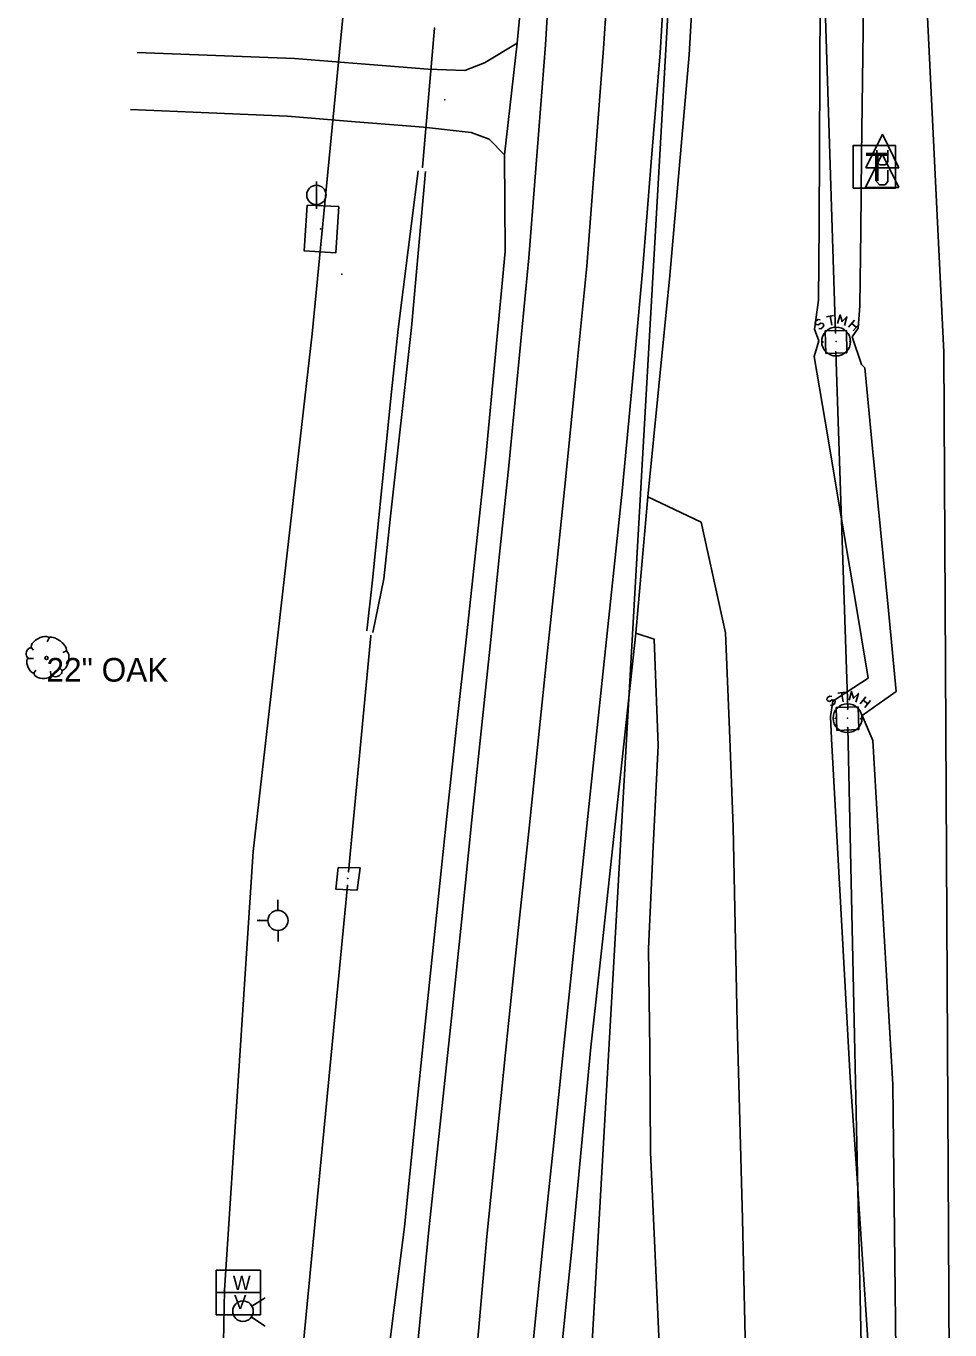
# Model space of a CAD drawing. Extents: x 1930288 to 1941089, y 588389 to 611475.
# Drawn here: x 1930793.7 to 1930989.2, y 598451.6 to 598727.5 of the extents above; entities that cross this region are included whole.
import ezdxf

# ---------------------------------------------------------------- set-up
doc = ezdxf.new("R2010")
doc.units = 0
for name, color, linetype in [('S_BASELINE', 7, 'Continuous'), ('S_DITCHLINE', 7, 'Continuous'), ('S_DRG_PT_SYM', 7, 'Continuous'), ('S_DRIVEWAY', 7, 'Continuous'), ('S_DROP_INLET', 7, 'Continuous'), ('S_EDGE_CONCRETE', 7, 'Continuous'), ('S_EDGE_PAVEMENT', 7, 'Continuous'), ('S_MSC_PT_SYM', 7, 'Continuous'), ('S_PAVEMENT_CROWN', 7, 'Continuous'), ('S_SANITARY_SEWER', 7, 'Continuous'), ('S_SHOULDER', 7, 'Continuous'), ('S_SIDE_DRAIN', 7, 'Continuous'), ('S_STORM_SEWER', 7, 'Continuous'), ('S_TELEPHONE_UTILITIES', 7, 'Continuous'), ('S_TREE', 7, 'Continuous'), ('S_TREE_ANNOT', 7, 'Continuous'), ('S_UNDERGROUND_CABLE', 7, 'Continuous'), ('S_UTILITY_POLE', 7, 'Continuous'), ('S_UTL_PT_SYM', 7, 'Continuous'), ('S_WATER_UTILITIES', 7, 'Continuous')]:
    doc.layers.add(name, color=color, linetype=linetype)

msp = doc.modelspace()

# ---------------------------------------------------------------- linework, layer by layer
at = {"layer": 'S_BASELINE'}
msp.add_line((1930894.27, 598110.49), (1930946.09, 599020.44), dxfattribs=at)
at = {"layer": 'S_DITCHLINE'}
for points in [[(1930961.8, 598733.51), (1930961.71, 598717.5), (1930961.63, 598701.5), (1930961.54, 598685.49), (1930961.45, 598669.49), (1930960.6, 598663.4), (1930961.51, 598660.89), (1930960.5, 598657.61), (1930963.36, 598640.59), (1930966.22, 598623.57), (1930969.09, 598606.55), (1930971.95, 598589.53), (1930964.42, 598584.67), (1930963.99, 598581.42), (1930964.18, 598576.71), (1930965.17, 598558.78), (1930966.16, 598540.86), (1930967.15, 598522.93), (1930968.14, 598505.01), (1930969.43, 598485.78), (1930970.71, 598466.55), (1930972, 598447.33)], [(1930970.91, 598731.9), (1930970.72, 598716.01), (1930970.54, 598700.12), (1930970.36, 598684.23), (1930970.18, 598668.34), (1930969.78, 598663.58), (1930968.54, 598661.77), (1930970.49, 598655.92), (1930971.21, 598655.22), (1930972.88, 598638.09), (1930974.55, 598620.96), (1930976.21, 598603.83), (1930977.88, 598586.7), (1930970.67, 598581.64), (1930972.93, 598576.35), (1930973.98, 598558.14), (1930975.03, 598539.93), (1930976.08, 598521.73), (1930977.13, 598503.52), (1930977.35, 598484.74), (1930977.56, 598465.96), (1930977.77, 598447.19)], [(1930876.67, 598696.88), (1930874.56, 598680.13), (1930872.44, 598663.37), (1930871.08, 598650.09), (1930869.72, 598636.8), (1930868.36, 598623.52), (1930867, 598610.24), (1930865.86, 598599.56)], [(1930878.23, 598696.7), (1930876.76, 598680.21), (1930875.28, 598663.71), (1930873.81, 598650.42), (1930872.34, 598637.12), (1930870.87, 598623.83), (1930869.4, 598610.54), (1930867.1, 598599.2)]]:
    msp.add_lwpolyline(points, dxfattribs=at)
at = {"layer": 'S_DRG_PT_SYM'}
for points in [[(1930880.15, 598727.06), (1930880.15, 598727.11), (1930880.15, 598727.06), (1930880.1, 598727.06), (1930880.15, 598727.06), (1930880.15, 598727.01), (1930880.15, 598727.06), (1930880.2, 598727.06)], [(1930877.61, 598697.64), (1930877.61, 598697.69), (1930877.61, 598697.64), (1930877.56, 598697.64), (1930877.61, 598697.64), (1930877.61, 598697.58), (1930877.61, 598697.64), (1930877.66, 598697.64)], [(1930866.67, 598598.49), (1930866.67, 598598.54), (1930866.67, 598598.49), (1930866.62, 598598.49), (1930866.67, 598598.49), (1930866.67, 598598.44), (1930866.67, 598598.49), (1930866.72, 598598.49)], [(1930861.78, 598547.12), (1930861.78, 598547.17), (1930861.78, 598547.12), (1930861.73, 598547.12), (1930861.78, 598547.12), (1930861.78, 598547.07), (1930861.78, 598547.12), (1930861.83, 598547.12)]]:
    msp.add_lwpolyline(points, dxfattribs=at)
at = {"layer": 'S_DRIVEWAY'}
for points in [[(1930897.67, 598723.87), (1930890.76, 598719.75), (1930886.59, 598718.14), (1930878.82, 598718.39), (1930864.66, 598719.5), (1930850.51, 598720.61), (1930833.87, 598721.28), (1930817.23, 598721.95)], [(1930815.79, 598709.82), (1930832.4, 598709.13), (1930849.02, 598708.44), (1930863.42, 598707.27), (1930877.81, 598706.1), (1930887.94, 598705.01), (1930891.69, 598703.54), (1930894.96, 598700.28)]]:
    msp.add_lwpolyline(points, dxfattribs=at)
at = {"layer": 'S_DROP_INLET'}
for points in [[(1930962.97, 598658.25), (1930962.86, 598663.03), (1930967.35, 598663.08), (1930967.43, 598658.33)], [(1930967.43, 598658.33), (1930962.97, 598658.25)], [(1930969.84, 598583.46), (1930965.19, 598583.3)], [(1930965.19, 598583.3), (1930965.32, 598578.46), (1930969.93, 598578.64), (1930969.84, 598583.46)], [(1930859.77, 598549.45), (1930859.26, 598544.89), (1930863.76, 598544.66), (1930864.39, 598549.38)], [(1930864.39, 598549.38), (1930859.77, 598549.45)]]:
    msp.add_lwpolyline(points, dxfattribs=at)
at = {"layer": 'S_EDGE_CONCRETE'}
for points in [[(1930853.24, 598689.61), (1930852.6, 598679.92), (1930859.27, 598679.52), (1930859.91, 598689.36)], [(1930859.91, 598689.36), (1930853.24, 598689.61)]]:
    msp.add_lwpolyline(points, dxfattribs=at)
at = {"layer": 'S_EDGE_PAVEMENT'}
for points in [[(1930904.92, 598744.7), (1930903.67, 598723.53), (1930901.89, 598701), (1930900.1, 598678.48), (1930897.99, 598656.48), (1930895.88, 598634.48), (1930893.93, 598615.75), (1930891.98, 598597.02), (1930890.03, 598578.29), (1930888.08, 598559.56), (1930885.91, 598538.55), (1930883.74, 598517.54), (1930881.36, 598495.14), (1930878.97, 598472.74), (1930877.33, 598456.1), (1930875.68, 598439.46)], [(1930929.16, 598742.91), (1930927.89, 598721.82), (1930926.03, 598698.68), (1930924.17, 598675.54), (1930922.04, 598652.3), (1930919.9, 598629.06), (1930917.99, 598611.04), (1930916.07, 598593.01), (1930914.16, 598574.98), (1930912.24, 598556.95), (1930909.92, 598534.68), (1930907.6, 598512.4), (1930905.38, 598491.18), (1930903.15, 598469.95), (1930901.49, 598453.28), (1930899.84, 598436.61)], [(1930925.3, 598627.92), (1930936.56, 598622.51), (1930941.76, 598599.13), (1930942.55, 598578.56), (1930943.33, 598557.99), (1930943.76, 598537.25), (1930944.18, 598516.5), (1930944.75, 598495.82), (1930945.32, 598475.13), (1930945.82, 598453.1), (1930946.32, 598431.07), (1930946.01, 598409.55), (1930945.7, 598388.03), (1930944.74, 598367.17), (1930943.78, 598346.31)], [(1930924.96, 598333.18), (1930925.73, 598350.75), (1930926.49, 598368.33), (1930927.26, 598385.9), (1930928.03, 598403.47), (1930927.92, 598424.51), (1930927.81, 598445.55), (1930926.85, 598467.37), (1930925.9, 598489.18), (1930925.69, 598510.76), (1930925.47, 598532.34), (1930926.46, 598553.81), (1930927.46, 598575.27), (1930926.63, 598597.79), (1930922.74, 598599.04)]]:
    msp.add_lwpolyline(points, dxfattribs=at)
at = {"layer": 'S_MSC_PT_SYM'}
for points in [[(1930882.32, 598711.9), (1930882.32, 598711.95), (1930882.32, 598711.9), (1930882.27, 598711.9), (1930882.32, 598711.9), (1930882.32, 598711.85), (1930882.32, 598711.9), (1930882.37, 598711.9)], [(1930856.07, 598684.59), (1930856.07, 598684.64), (1930856.07, 598684.59), (1930856.02, 598684.59), (1930856.07, 598684.59), (1930856.07, 598684.54), (1930856.07, 598684.59), (1930856.12, 598684.59)], [(1930965.03, 598662.59), (1930965.03, 598662.64), (1930965.03, 598662.59), (1930964.98, 598662.59), (1930965.03, 598662.59), (1930965.03, 598662.54), (1930965.03, 598662.59), (1930965.08, 598662.59)], [(1930962.35, 598660.66), (1930962.35, 598660.71), (1930962.35, 598660.66), (1930962.3, 598660.66), (1930962.35, 598660.66), (1930962.35, 598660.61), (1930962.35, 598660.66), (1930962.4, 598660.66)], [(1930965.07, 598658.54), (1930965.07, 598658.59), (1930965.07, 598658.54), (1930965.02, 598658.54), (1930965.07, 598658.54), (1930965.07, 598658.49), (1930965.07, 598658.54), (1930965.12, 598658.54)], [(1930968.04, 598660.78), (1930968.04, 598660.83), (1930968.04, 598660.78), (1930967.99, 598660.78), (1930968.04, 598660.78), (1930968.04, 598660.73), (1930968.04, 598660.78), (1930968.09, 598660.78)], [(1930964.99, 598581.03), (1930964.99, 598581.08), (1930964.99, 598581.03), (1930964.94, 598581.03), (1930964.99, 598581.03), (1930964.99, 598580.98), (1930964.99, 598581.03), (1930965.04, 598581.03)], [(1930967.6, 598582.99), (1930967.6, 598583.04), (1930967.6, 598582.99), (1930967.55, 598582.99), (1930967.6, 598582.99), (1930967.6, 598582.94), (1930967.6, 598582.99), (1930967.65, 598582.99)], [(1930970.34, 598580.95), (1930970.34, 598581), (1930970.34, 598580.95), (1930970.29, 598580.95), (1930970.34, 598580.95), (1930970.34, 598580.9), (1930970.34, 598580.95), (1930970.39, 598580.95)], [(1930967.6, 598579.05), (1930967.6, 598579.1), (1930967.6, 598579.05), (1930967.55, 598579.05), (1930967.6, 598579.05), (1930967.6, 598579), (1930967.6, 598579.05), (1930967.65, 598579.05)], [(1930861.97, 598548.55), (1930861.97, 598548.6), (1930861.97, 598548.55), (1930861.92, 598548.55), (1930861.97, 598548.55), (1930861.97, 598548.5), (1930861.97, 598548.55), (1930862.02, 598548.55)], [(1930861.75, 598545.64), (1930861.75, 598545.69), (1930861.75, 598545.64), (1930861.7, 598545.64), (1930861.75, 598545.64), (1930861.75, 598545.59), (1930861.75, 598545.64), (1930861.8, 598545.64)]]:
    msp.add_lwpolyline(points, dxfattribs=at)
at = {"layer": 'S_PAVEMENT_CROWN'}
msp.add_lwpolyline([(1930917.3, 598743.97), (1930915.93, 598722.77), (1930914.15, 598699.75), (1930912.37, 598676.73), (1930910.11, 598654.11), (1930907.86, 598631.49), (1930905.94, 598613.07), (1930904.03, 598594.64), (1930902.11, 598576.22), (1930900.2, 598557.8), (1930897.89, 598536.1), (1930895.58, 598514.41), (1930893.41, 598492.88), (1930891.24, 598471.35), (1930890.05, 598457.73), (1930888.86, 598444.11)], dxfattribs=at)
at = {"layer": 'S_SANITARY_SEWER'}
for p, q in [((1930987.94, 598658.53), (1930979.26, 598838.38)), ((1930989.23, 598417.74), (1930987.94, 598658.53))]:
    msp.add_line(p, q, dxfattribs=at)
at = {"layer": 'S_SHOULDER'}
for points in [[(1930899.62, 598745.09), (1930897.67, 598723.87), (1930894.96, 598700.28), (1930895.14, 598679.79), (1930893.09, 598658.06), (1930891.04, 598636.33), (1930888.96, 598617.3), (1930886.89, 598598.27), (1930884.81, 598579.25), (1930882.73, 598560.22), (1930880.55, 598539.26), (1930878.36, 598518.31), (1930876.07, 598495.86), (1930873.77, 598473.4), (1930871.29, 598453.49), (1930868.81, 598433.59)], [(1930935.25, 598742.5), (1930934.05, 598721.41), (1930932.02, 598698.07), (1930929.98, 598674.73), (1930927.64, 598651.32), (1930925.3, 598627.92), (1930924.02, 598613.48), (1930922.74, 598599.04), (1930920.43, 598577.54), (1930918.13, 598556.04), (1930915.69, 598533.74), (1930913.25, 598511.45), (1930911.26, 598490.47), (1930909.27, 598469.49), (1930907.6, 598452.98), (1930905.93, 598436.47)]]:
    msp.add_lwpolyline(points, dxfattribs=at)
at = {"layer": 'S_SIDE_DRAIN'}
for p, q in [((1930880.15, 598727.06), (1930877.61, 598697.64)), ((1930866.67, 598598.49), (1930861.97, 598548.55))]:
    msp.add_line(p, q, dxfattribs=at)
at = {"layer": 'S_STORM_SEWER'}
for p, q in [((1930959.85, 598826.59), (1930965.03, 598662.59)), ((1930960.82, 598665.04), (1930960.74, 598664.65)), ((1930960.74, 598664.65), (1930960.93, 598664.38)), ((1930961.36, 598665.43), (1930960.82, 598665.04)), ((1930960.93, 598664.38), (1930961.36, 598664.27)), ((1930961.79, 598665.35), (1930961.36, 598665.43)), ((1930961.36, 598664.27), (1930961.9, 598664.61)), ((1930961.9, 598664.61), (1930962.37, 598664.54)), ((1930962.44, 598663.84), (1930961.9, 598663.45)), ((1930962.37, 598664.54), (1930962.52, 598664.27)), ((1930962.52, 598664.27), (1930962.44, 598663.84)), ((1930963.1, 598666.01), (1930964.61, 598666.28)), ((1930963.88, 598666.16), (1930964.23, 598664.23)), ((1930967.79, 598663.8), (1930969.03, 598665.27)), ((1930968.45, 598664.58), (1930969.42, 598663.76)), ((1930970, 598664.46), (1930968.76, 598662.99)), ((1930961.9, 598663.45), (1930961.51, 598663.53)), ((1930965.07, 598658.54), (1930967.6, 598582.99)), ((1930965.53, 598586.31), (1930967.04, 598586.58)), ((1930966.3, 598586.47), (1930966.65, 598584.53)), ((1930963.24, 598585.34), (1930963.16, 598584.96)), ((1930963.16, 598584.96), (1930963.36, 598584.69)), ((1930963.78, 598585.73), (1930963.24, 598585.34)), ((1930963.36, 598584.69), (1930963.78, 598584.57)), ((1930964.21, 598585.65), (1930963.78, 598585.73)), ((1930963.78, 598584.57), (1930964.33, 598584.92)), ((1930964.33, 598583.76), (1930963.94, 598583.83)), ((1930964.33, 598584.92), (1930964.79, 598584.84)), ((1930964.87, 598584.14), (1930964.33, 598583.76)), ((1930964.79, 598584.84), (1930964.95, 598584.57)), ((1930964.95, 598584.57), (1930964.87, 598584.14)), ((1930970.22, 598584.1), (1930971.46, 598585.58)), ((1930970.88, 598584.88), (1930971.84, 598584.07)), ((1930972.43, 598584.76), (1930971.19, 598583.29)), ((1930967.6, 598579.05), (1930971.17, 598413.62)), ((1930861.75, 598545.64), (1930852.09, 598445.29))]:
    msp.add_line(p, q, dxfattribs=at)
for points in [[(1930966.9, 598664.11), (1930967.44, 598665.97), (1930966.4, 598664.96), (1930966.01, 598666.4), (1930965.47, 598664.54)], [(1930969.33, 598584.41), (1930969.87, 598586.27), (1930968.82, 598585.27), (1930968.43, 598586.7), (1930967.89, 598584.84)]]:
    msp.add_lwpolyline(points, dxfattribs=at)
for centre in [(1930965.14, 598660.74), (1930967.57, 598581.04)]:
    msp.add_circle(centre, 3.05, dxfattribs=at)
at = {"layer": 'S_TELEPHONE_UTILITIES'}
msp.add_lwpolyline([(1930968.75, 598693.21), (1930968.75, 598702.21), (1930977.75, 598702.21), (1930977.75, 598693.21)], close=True, dxfattribs=at)
at = {"layer": 'S_TREE'}
for p, q in [((1930798.6, 598598.02), (1930798.21, 598597.17)), ((1930794.8, 598596.01), (1930795.3, 598595.43)), ((1930802.16, 598595.23), (1930801.5, 598594.96)), ((1930794.14, 598593.68), (1930795.27, 598593.68)), ((1930795.3, 598590.5), (1930795.77, 598591.2)), ((1930798.99, 598590.23), (1930798.91, 598591.01)), ((1930801.39, 598591.12), (1930800.92, 598591.55))]:
    msp.add_line(p, q, dxfattribs=at)
msp.add_circle((1930798.04, 598593.78), 0.341, dxfattribs=at)
for centre, major_axis, ratio, start_param, end_param in [((1930796.7, 598596.98), (1.86, 1.08), 0.471018, 0, 3.141593), ((1930800.36, 598596.66), (-1.81, 1.36), 0.405113, 3.141593, 6.283186), ((1930794.47, 598594.86), (0.31, 1.03), 0.646762, 0, 3.141593), ((1930801.71, 598593.25), (0.46, 2.04), 0.482994, 3.141593, 6.283185), ((1930794.77, 598592.21), (-0.61, 1.6), 0.420543, 6.283185, 9.424777), ((1930797.23, 598590.43), (-1.83, 0.19), 0.529943, 0, 3.141593), ((1930800.19, 598590.73), (1.09, 0.46), 0.711534, 3.141592, 6.283185)]:
    msp.add_ellipse(centre, major_axis=major_axis, ratio=ratio, start_param=start_param, end_param=end_param, dxfattribs=at)
at = {"layer": 'S_UNDERGROUND_CABLE'}
for p, q in [((1930974.95, 598704.63), (1930971.43, 598697.54)), ((1930974.95, 598704.63), (1930978.44, 598697.54)), ((1930974.92, 598700.45), (1930971.39, 598693.36)), ((1930973.75, 598698.78), (1930973.75, 598701.22)), ((1930974.92, 598700.45), (1930978.4, 598693.36)), ((1930976.11, 598701.22), (1930976.11, 598698.78)), ((1930971.43, 598697.54), (1930978.44, 598697.54)), ((1930973.71, 598694.6), (1930973.71, 598697.04)), ((1930974.37, 598698.12), (1930973.75, 598698.78)), ((1930975.57, 598698.12), (1930974.37, 598698.12)), ((1930976.11, 598698.78), (1930975.57, 598698.12)), ((1930976.08, 598697.04), (1930976.08, 598694.6)), ((1930974.33, 598693.94), (1930973.71, 598694.6)), ((1930976.08, 598694.6), (1930975.54, 598693.94)), ((1930971.39, 598693.36), (1930978.4, 598693.36)), ((1930975.54, 598693.94), (1930974.33, 598693.94))]:
    msp.add_line(p, q, dxfattribs=at)
at = {"layer": 'S_UTILITY_POLE'}
for p, q in [((1930855.16, 598688.84), (1930855.16, 598694.63)), ((1930847.01, 598540.35), (1930847.01, 598542.6)), ((1930844.92, 598538.22), (1930842.6, 598538.22)), ((1930847.09, 598533.8), (1930847.09, 598536.13))]:
    msp.add_line(p, q, dxfattribs=at)
for centre, radius in [((1930855.16, 598691.77), 2.05), ((1930847.02, 598538.24), 2.13)]:
    msp.add_circle(centre, radius, dxfattribs=at)
at = {"layer": 'S_UTL_PT_SYM'}
for points in [[(1930860.55, 598675.02), (1930860.55, 598675.07), (1930860.55, 598675.02), (1930860.5, 598675.02), (1930860.55, 598675.02), (1930860.55, 598674.97), (1930860.55, 598675.02), (1930860.6, 598675.02)], [(1930854.29, 598662.35), (1930854.29, 598662.4), (1930854.29, 598662.35), (1930854.24, 598662.35), (1930854.29, 598662.35), (1930854.29, 598662.3), (1930854.29, 598662.35), (1930854.34, 598662.35)], [(1930965.03, 598662.59), (1930965.03, 598662.64), (1930965.03, 598662.59), (1930964.98, 598662.59), (1930965.03, 598662.59), (1930965.03, 598662.54), (1930965.03, 598662.59), (1930965.08, 598662.59)], [(1930965.07, 598658.54), (1930965.07, 598658.59), (1930965.07, 598658.54), (1930965.02, 598658.54), (1930965.07, 598658.54), (1930965.07, 598658.49), (1930965.07, 598658.54), (1930965.12, 598658.54)], [(1930965.14, 598660.74), (1930965.14, 598660.79), (1930965.14, 598660.74), (1930965.09, 598660.74), (1930965.14, 598660.74), (1930965.14, 598660.69), (1930965.14, 598660.74), (1930965.19, 598660.74)], [(1930987.94, 598658.53), (1930987.94, 598658.58), (1930987.94, 598658.53), (1930987.89, 598658.53), (1930987.94, 598658.53), (1930987.94, 598658.47), (1930987.94, 598658.53), (1930987.99, 598658.53)], [(1930967.57, 598581.04), (1930967.57, 598581.09), (1930967.57, 598581.04), (1930967.52, 598581.04), (1930967.57, 598581.04), (1930967.57, 598580.99), (1930967.57, 598581.04), (1930967.62, 598581.04)], [(1930967.6, 598582.99), (1930967.6, 598583.04), (1930967.6, 598582.99), (1930967.55, 598582.99), (1930967.6, 598582.99), (1930967.6, 598582.94), (1930967.6, 598582.99), (1930967.65, 598582.99)], [(1930967.6, 598579.05), (1930967.6, 598579.1), (1930967.6, 598579.05), (1930967.55, 598579.05), (1930967.6, 598579.05), (1930967.6, 598579), (1930967.6, 598579.05), (1930967.65, 598579.05)], [(1930841.77, 598552.81), (1930841.77, 598552.86), (1930841.77, 598552.81), (1930841.72, 598552.81), (1930841.77, 598552.81), (1930841.77, 598552.76), (1930841.77, 598552.81), (1930841.82, 598552.81)], [(1930861.97, 598548.55), (1930861.97, 598548.6), (1930861.97, 598548.55), (1930861.92, 598548.55), (1930861.97, 598548.55), (1930861.97, 598548.5), (1930861.97, 598548.55), (1930862.02, 598548.55)], [(1930861.75, 598545.64), (1930861.75, 598545.69), (1930861.75, 598545.64), (1930861.7, 598545.64), (1930861.75, 598545.64), (1930861.75, 598545.59), (1930861.75, 598545.64), (1930861.8, 598545.64)], [(1930861.78, 598547.12), (1930861.78, 598547.17), (1930861.78, 598547.12), (1930861.73, 598547.12), (1930861.78, 598547.12), (1930861.78, 598547.07), (1930861.78, 598547.12), (1930861.83, 598547.12)], [(1930843.17, 598538.3), (1930843.17, 598538.35), (1930843.17, 598538.3), (1930843.12, 598538.3), (1930843.17, 598538.3), (1930843.17, 598538.25), (1930843.17, 598538.3), (1930843.22, 598538.3)], [(1930835.68, 598459.98), (1930835.68, 598460.03), (1930835.68, 598459.98), (1930835.63, 598459.98), (1930835.68, 598459.98), (1930835.68, 598459.93), (1930835.68, 598459.98), (1930835.73, 598459.98)]]:
    msp.add_lwpolyline(points, dxfattribs=at)
at = {"layer": 'S_WATER_UTILITIES'}
for p, q in [((1930871.67, 598842.11), (1930854.29, 598662.35)), ((1930854.29, 598662.35), (1930841.77, 598552.81)), ((1930841.77, 598552.81), (1930835.68, 598459.98)), ((1930833.92, 598464.23), (1930843.33, 598464.23)), ((1930833.92, 598454.81), (1930833.92, 598464.23)), ((1930843.33, 598464.23), (1930843.33, 598454.81)), ((1930835.68, 598459.98), (1930831.37, 598238.21)), ((1930833.92, 598459.54), (1930843.33, 598459.54)), ((1930841.52, 598456.62), (1930844.35, 598458.35)), ((1930843.33, 598454.81), (1930833.92, 598454.81)), ((1930841.4, 598454.31), (1930844.31, 598452.38))]:
    msp.add_line(p, q, dxfattribs=at)
msp.add_circle((1930839.62, 598455.56), 2.18, dxfattribs=at)

# ---------------------------------------------------------------- texts
at = {"layer": 'S_TELEPHONE_UTILITIES'}
msp.add_text('T', height=6, rotation=360, dxfattribs=at).set_placement((1930971.31, 598694.71))
at = {"layer": 'S_TREE_ANNOT'}
msp.add_text('22" OAK', height=5, dxfattribs=at).set_placement((1930798.04, 598588.78))
at = {"layer": 'S_WATER_UTILITIES'}
for s, p in [('W', (1930837.47, 598460.07)), ('V', (1930837.7, 598456.01))]:
    msp.add_text(s, height=3, rotation=360, dxfattribs=at).set_placement(p)

doc.saveas('drawing.dxf')
